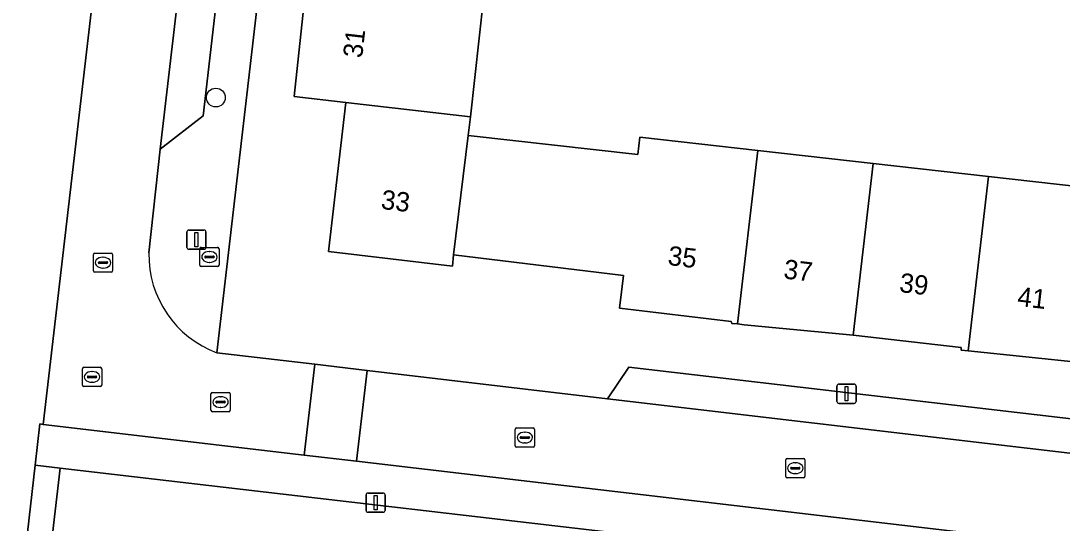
# Model space of a CAD drawing. Extents: x 161241 to 161758, y 384138 to 384885.
# Drawn here: x 161339.7 to 161393.7, y 384501.4 to 384527.4 of the extents above; entities that cross this region are included whole.
import ezdxf

# ---------------------------------------------------------------- set-up
doc = ezdxf.new("R2010")
doc.units = 0
for name, color, linetype in [('IMGEO_Boom', 7, 'Continuous'), ('IMGEO_Brandkraan', 7, 'Continuous'), ('IMGEO_Erf', 7, 'Continuous'), ('IMGEO_Kolk', 7, 'Continuous'), ('IMGEO_Lichtmast', 7, 'Continuous'), ('IMGEO_Pand', 7, 'Continuous'), ('IMGEO_Pand_nummerreeks', 7, 'Continuous'), ('IMGEO_Parkeervlak_open', 7, 'Continuous'), ('IMGEO_Rijbaan_lokaal_open', 7, 'Continuous'), ('IMGEO_Rioolput', 7, 'Continuous'), ('IMGEO_Voetpad_open', 7, 'Continuous')]:
    doc.layers.add(name, color=color, linetype=linetype)

msp = doc.modelspace()

# ---------------------------------------------------------------- linework, layer by layer
at = {"layer": 'IMGEO_Boom'}
msp.add_circle((161349.789, 384523.448), 0.489, dxfattribs=at)
at = {"layer": 'IMGEO_Brandkraan'}
for p, q in [((161348.955, 384514.751), (161348.955, 384515.603)), ((161349.03, 384515.677), (161349.882, 384515.677)), ((161349.443, 384515.457), (161349.468, 384515.457)), ((161349.956, 384515.603), (161349.956, 384514.751)), ((161349.214, 384515.171), (161349.214, 384515.183)), ((161349.652, 384515.134), (161349.254, 384515.134)), ((161349.257, 384515.22), (161349.655, 384515.22)), ((161349.466, 384514.897), (161349.441, 384514.897)), ((161349.698, 384515.183), (161349.698, 384515.171)), ((161349.882, 384514.677), (161349.03, 384514.677))]:
    msp.add_line(p, q, dxfattribs=at)
for points in [[(161348.955, 384514.751), (161348.955, 384515.603)], [(161349.03, 384515.677), (161349.882, 384515.677)], [(161349.956, 384515.603), (161349.956, 384514.751)], [(161349.882, 384514.677), (161349.03, 384514.677)]]:
    msp.add_lwpolyline(points, dxfattribs=at)
for centre, radius, start, end in [((161349.032, 384515.601), 0.0765, 91.552, 178.448), ((161349.032, 384515.601), 0.0765, 91.552, 178.448), ((161349.88, 384515.601), 0.0765, 1.552, 88.448), ((161349.88, 384515.601), 0.0765, 1.552, 88.448), ((161349.254, 384515.18), 0.0403, 85.8775, 175.7526), ((161349.251, 384515.17), 0.0366, 178.938, 274.7102), ((161349.655, 384515.177), 0.043, 264.8664, 352.4533), ((161349.659, 384515.182), 0.0386, 1.7309, 96.639), ((161349.032, 384514.753), 0.0765, 181.552, 268.448), ((161349.032, 384514.753), 0.0765, 181.552, 268.448), ((161349.88, 384514.753), 0.0765, 271.552, 358.448), ((161349.88, 384514.753), 0.0765, 271.552, 358.448)]:
    msp.add_arc(centre, radius, start, end, dxfattribs=at)
for centre, major_axis, ratio, start_param, end_param in [((161349.442, 384515.177), (-0.387, 0.002), 0.722429, 4.712389, 7.853982), ((161349.467, 384515.177), (-0.39, 0.002), 0.717154, 1.570796, 4.712389)]:
    msp.add_ellipse(centre, major_axis=major_axis, ratio=ratio, start_param=start_param, end_param=end_param, dxfattribs=at)
at = {"layer": 'IMGEO_Erf'}
for points in [[(161332.131, 384432.245), (161332.897, 384438.907), (161336.632, 384471.394), (161336.946, 384474.139), (161340.403, 384504.377), (161340.647, 384506.515), (161340.82, 384506.489), (161349.943, 384584.816), (161350.191, 384586.943), (161382.92, 384583.217)], [(161353.642, 384542.948), (161349.844, 384510.209), (161354.929, 384509.609), (161357.65, 384509.288), (161370.122, 384507.816), (161371.245, 384509.461), (161423.885, 384503.32), (161424.463, 384501.437), (161427.862, 384501.04), (161430.603, 384500.72), (161436.769, 384500)], [(161363.697, 384528.581), (161363.009, 384522.448), (161362.9, 384521.481), (161371.708, 384520.492), (161371.808, 384521.386), (161377.931, 384520.699), (161383.926, 384520.026), (161389.92, 384519.353), (161395.914, 384518.68), (161401.908, 384518.007), (161407.903, 384517.334), (161413.897, 384516.661), (161419.892, 384515.989), (161426.097, 384515.292), (161425.996, 384514.397), (161434.78, 384513.411), (161434.849, 384514.022), (161435.538, 384520.166), (161436.213, 384526.177), (161436.887, 384532.189)], [(161394.858, 384509.685), (161388.859, 384510.31), (161388.492, 384510.348), (161388.492, 384510.475), (161382.88, 384511.115), (161377.225, 384511.664), (161376.875, 384511.701), (161376.584, 384511.732), (161376.552, 384511.837), (161370.746, 384512.522), (161370.953, 384514.221), (161362.13, 384515.29), (161362.078, 384514.704), (161355.646, 384515.453), (161356.534, 384523.195), (161353.849, 384523.505), (161354.513, 384529.66)], [(161377.935, 384500), (161341.704, 384504.225), (161338.179, 384473.999)]]:
    msp.add_lwpolyline(points, dxfattribs=at)
at = {"layer": 'IMGEO_Kolk'}
for p, q in [((161343.502, 384515.382), (161344.354, 384515.382)), ((161343.427, 384514.456), (161343.427, 384515.308)), ((161343.686, 384514.876), (161343.686, 384514.888)), ((161344.124, 384514.839), (161343.726, 384514.839)), ((161343.729, 384514.925), (161344.127, 384514.925)), ((161343.915, 384515.162), (161343.94, 384515.162)), ((161344.17, 384514.888), (161344.17, 384514.876)), ((161344.428, 384515.308), (161344.428, 384514.456)), ((161344.354, 384514.382), (161343.502, 384514.382)), ((161343.938, 384514.602), (161343.913, 384514.602)), ((161349.535, 384507.22), (161349.535, 384508.072)), ((161349.61, 384508.146), (161350.462, 384508.146)), ((161350.023, 384507.926), (161350.048, 384507.926)), ((161350.536, 384508.072), (161350.536, 384507.22)), ((161349.794, 384507.64), (161349.794, 384507.652)), ((161350.232, 384507.603), (161349.834, 384507.603)), ((161349.837, 384507.689), (161350.235, 384507.689)), ((161350.046, 384507.366), (161350.021, 384507.366)), ((161350.278, 384507.652), (161350.278, 384507.64)), ((161350.462, 384507.146), (161349.61, 384507.146)), ((161365.337, 384505.38), (161365.337, 384506.232)), ((161365.412, 384506.306), (161366.264, 384506.306)), ((161366.338, 384506.232), (161366.338, 384505.38)), ((161365.596, 384505.8), (161365.596, 384505.812)), ((161366.034, 384505.763), (161365.636, 384505.763)), ((161365.639, 384505.849), (161366.037, 384505.849)), ((161365.825, 384506.086), (161365.85, 384506.086)), ((161366.08, 384505.812), (161366.08, 384505.8)), ((161366.264, 384505.306), (161365.412, 384505.306)), ((161365.848, 384505.526), (161365.823, 384505.526)), ((161379.383, 384503.792), (161379.383, 384504.644)), ((161379.458, 384504.718), (161380.31, 384504.718)), ((161380.384, 384504.644), (161380.384, 384503.792)), ((161379.642, 384504.212), (161379.642, 384504.224)), ((161380.08, 384504.175), (161379.682, 384504.175)), ((161379.685, 384504.261), (161380.083, 384504.261)), ((161379.871, 384504.498), (161379.896, 384504.498)), ((161380.126, 384504.224), (161380.126, 384504.212)), ((161380.31, 384503.718), (161379.458, 384503.718)), ((161379.894, 384503.938), (161379.869, 384503.938))]:
    msp.add_line(p, q, dxfattribs=at)
for points in [[(161343.502, 384515.382), (161344.354, 384515.382)], [(161343.427, 384514.456), (161343.427, 384515.308)], [(161344.428, 384515.308), (161344.428, 384514.456)], [(161344.354, 384514.382), (161343.502, 384514.382)], [(161349.535, 384507.22), (161349.535, 384508.072)], [(161349.61, 384508.146), (161350.462, 384508.146)], [(161350.536, 384508.072), (161350.536, 384507.22)], [(161350.462, 384507.146), (161349.61, 384507.146)], [(161365.337, 384505.38), (161365.337, 384506.232)], [(161365.412, 384506.306), (161366.264, 384506.306)], [(161366.338, 384506.232), (161366.338, 384505.38)], [(161366.264, 384505.306), (161365.412, 384505.306)], [(161379.383, 384503.792), (161379.383, 384504.644)], [(161379.458, 384504.718), (161380.31, 384504.718)], [(161380.384, 384504.644), (161380.384, 384503.792)], [(161380.31, 384503.718), (161379.458, 384503.718)]]:
    msp.add_lwpolyline(points, dxfattribs=at)
for centre, radius, start, end in [((161343.504, 384515.306), 0.0765, 91.552, 178.448), ((161343.504, 384515.306), 0.0765, 91.552, 178.448), ((161344.352, 384515.306), 0.0765, 1.552, 88.448), ((161344.352, 384515.306), 0.0765, 1.552, 88.448), ((161343.726, 384514.885), 0.0403, 85.8775, 175.7526), ((161343.723, 384514.875), 0.0366, 178.938, 274.7102), ((161344.127, 384514.882), 0.043, 264.8664, 352.4533), ((161344.131, 384514.887), 0.0386, 1.7309, 96.639), ((161343.504, 384514.458), 0.0765, 181.552, 268.448), ((161343.504, 384514.458), 0.0765, 181.552, 268.448), ((161344.352, 384514.458), 0.0765, 271.552, 358.448), ((161344.352, 384514.458), 0.0765, 271.552, 358.448), ((161349.612, 384508.07), 0.0765, 91.552, 178.448), ((161349.612, 384508.07), 0.0765, 91.552, 178.448), ((161350.46, 384508.07), 0.0765, 1.552, 88.448), ((161350.46, 384508.07), 0.0765, 1.552, 88.448), ((161349.834, 384507.649), 0.0403, 85.8775, 175.7526), ((161349.831, 384507.639), 0.0366, 178.938, 274.7102), ((161350.235, 384507.646), 0.043, 264.8664, 352.4533), ((161350.239, 384507.651), 0.0386, 1.7309, 96.639), ((161349.612, 384507.222), 0.0765, 181.552, 268.448), ((161349.612, 384507.222), 0.0765, 181.552, 268.448), ((161350.46, 384507.222), 0.0765, 271.552, 358.448), ((161350.46, 384507.222), 0.0765, 271.552, 358.448), ((161365.414, 384506.23), 0.0765, 91.552, 178.448), ((161365.414, 384506.23), 0.0765, 91.552, 178.448), ((161366.262, 384506.23), 0.0765, 1.552, 88.448), ((161366.262, 384506.23), 0.0765, 1.552, 88.448), ((161365.636, 384505.809), 0.0403, 85.8775, 175.7526), ((161365.633, 384505.799), 0.0366, 178.938, 274.7102), ((161366.037, 384505.806), 0.043, 264.8664, 352.4533), ((161366.041, 384505.811), 0.0386, 1.7309, 96.639), ((161365.414, 384505.382), 0.0765, 181.552, 268.448), ((161365.414, 384505.382), 0.0765, 181.552, 268.448), ((161366.262, 384505.382), 0.0765, 271.552, 358.448), ((161366.262, 384505.382), 0.0765, 271.552, 358.448), ((161379.46, 384504.642), 0.0765, 91.552, 178.448), ((161379.46, 384504.642), 0.0765, 91.552, 178.448), ((161380.308, 384504.642), 0.0765, 1.552, 88.448), ((161380.308, 384504.642), 0.0765, 1.552, 88.448), ((161379.682, 384504.221), 0.0403, 85.8775, 175.7526), ((161379.679, 384504.211), 0.0366, 178.938, 274.7102), ((161380.083, 384504.218), 0.043, 264.8664, 352.4533), ((161380.087, 384504.223), 0.0386, 1.7309, 96.639), ((161379.46, 384503.794), 0.0765, 181.552, 268.448), ((161379.46, 384503.794), 0.0765, 181.552, 268.448), ((161380.308, 384503.794), 0.0765, 271.552, 358.448), ((161380.308, 384503.794), 0.0765, 271.552, 358.448)]:
    msp.add_arc(centre, radius, start, end, dxfattribs=at)
for centre, major_axis, ratio, start_param, end_param in [((161343.914, 384514.882), (-0.387, 0.002), 0.722429, 4.712389, 7.853982), ((161343.939, 384514.882), (-0.39, 0.002), 0.717154, 1.570796, 4.712389), ((161350.022, 384507.646), (-0.387, 0.002), 0.722429, 4.712389, 7.853982), ((161350.047, 384507.646), (-0.39, 0.002), 0.717154, 1.570796, 4.712389), ((161365.824, 384505.806), (-0.387, 0.002), 0.722429, 4.712389, 7.853982), ((161365.849, 384505.806), (-0.39, 0.002), 0.717154, 1.570796, 4.712389), ((161379.87, 384504.218), (-0.387, 0.002), 0.722429, 4.712389, 7.853982), ((161379.895, 384504.218), (-0.39, 0.002), 0.717154, 1.570796, 4.712389)]:
    msp.add_ellipse(centre, major_axis=major_axis, ratio=ratio, start_param=start_param, end_param=end_param, dxfattribs=at)
at = {"layer": 'IMGEO_Lichtmast'}
for p, q in [((161348.283, 384515.674), (161348.283, 384516.474)), ((161348.283, 384516.474), (161348.283, 384515.674)), ((161348.383, 384516.574), (161349.173, 384516.574)), ((161349.173, 384516.574), (161348.383, 384516.574)), ((161349.273, 384516.474), (161349.273, 384515.674)), ((161349.273, 384515.674), (161349.273, 384516.474)), ((161349.173, 384515.574), (161348.383, 384515.574)), ((161348.383, 384515.574), (161349.173, 384515.574)), ((161382.048, 384507.68), (161382.048, 384508.48)), ((161382.048, 384508.48), (161382.048, 384507.68)), ((161382.148, 384508.58), (161382.938, 384508.58)), ((161382.938, 384508.58), (161382.148, 384508.58)), ((161383.038, 384508.48), (161383.038, 384507.68)), ((161383.038, 384507.68), (161383.038, 384508.48)), ((161382.938, 384507.58), (161382.148, 384507.58)), ((161382.148, 384507.58), (161382.938, 384507.58)), ((161357.689, 384502.927), (161358.479, 384502.927)), ((161358.479, 384502.927), (161357.689, 384502.927)), ((161357.589, 384502.027), (161357.589, 384502.827)), ((161357.589, 384502.827), (161357.589, 384502.027)), ((161358.579, 384502.827), (161358.579, 384502.027)), ((161358.579, 384502.027), (161358.579, 384502.827)), ((161358.479, 384501.927), (161357.689, 384501.927)), ((161357.689, 384501.927), (161358.479, 384501.927))]:
    msp.add_line(p, q, dxfattribs=at)
for points in [[(161348.703, 384516.449), (161348.853, 384516.449), (161348.853, 384515.699), (161348.703, 384515.699), (161348.703, 384516.449)], [(161382.468, 384508.455), (161382.618, 384508.455), (161382.618, 384507.705), (161382.468, 384507.705), (161382.468, 384508.455)], [(161358.009, 384502.802), (161358.159, 384502.802), (161358.159, 384502.052), (161358.009, 384502.052), (161358.009, 384502.802)]]:
    msp.add_lwpolyline(points, dxfattribs=at)
for centre, start, end in [((161348.383, 384516.474), 90, 180), ((161348.383, 384516.474), 90, 180), ((161349.173, 384516.474), 0, 90), ((161349.173, 384516.474), 360, 90), ((161348.383, 384515.674), 180, 270), ((161348.383, 384515.674), 180, 270), ((161349.173, 384515.674), 270, 0), ((161349.173, 384515.674), 270, 0), ((161382.148, 384508.48), 90, 180), ((161382.148, 384508.48), 90, 180), ((161382.938, 384508.48), 0, 90), ((161382.938, 384508.48), 360, 90), ((161382.148, 384507.68), 180, 270), ((161382.148, 384507.68), 180, 270), ((161382.938, 384507.68), 270, 0), ((161382.938, 384507.68), 270, 0), ((161357.689, 384502.827), 90, 180), ((161357.689, 384502.827), 90, 180), ((161358.479, 384502.827), 0, 90), ((161358.479, 384502.827), 360, 90), ((161357.689, 384502.027), 180, 270), ((161357.689, 384502.027), 180, 270), ((161358.479, 384502.027), 270, 0), ((161358.479, 384502.027), 270, 0)]:
    msp.add_arc(centre, 0.1, start, end, dxfattribs=at)
at = {"layer": 'IMGEO_Pand'}
for points in [[(161354.513, 384529.66), (161353.849, 384523.505), (161356.534, 384523.195), (161363.009, 384522.448), (161363.697, 384528.581)], [(161362.9, 384521.481), (161363.009, 384522.448), (161356.534, 384523.195), (161355.646, 384515.453), (161362.078, 384514.704), (161362.13, 384515.29)], [(161377.931, 384520.699), (161371.808, 384521.386), (161371.708, 384520.492), (161362.9, 384521.481), (161362.13, 384515.29), (161370.953, 384514.221), (161370.746, 384512.522), (161376.552, 384511.837), (161376.584, 384511.732), (161376.875, 384511.701)], [(161376.875, 384511.701), (161377.225, 384511.664), (161382.88, 384511.115), (161383.926, 384520.026), (161377.931, 384520.699)], [(161389.92, 384519.353), (161383.926, 384520.026), (161382.88, 384511.115), (161388.492, 384510.475), (161388.492, 384510.348), (161388.859, 384510.31)], [(161388.859, 384510.31), (161394.858, 384509.685), (161395.914, 384518.68), (161389.92, 384519.353)]]:
    msp.add_lwpolyline(points, close=True, dxfattribs=at)
at = {"layer": 'IMGEO_Parkeervlak_open'}
for points in [[(161346.902, 384520.776), (161349.128, 384522.508), (161351.24, 384540.794), (161349.456, 384542.683)], [(161370.122, 384507.816), (161424.463, 384501.437), (161423.885, 384503.32), (161371.245, 384509.461)]]:
    msp.add_lwpolyline(points, close=True, dxfattribs=at)
at = {"layer": 'IMGEO_Rijbaan_lokaal_open'}
for points in [[(161382.841, 384581.101), (161349.943, 384584.816), (161340.82, 384506.489), (161354.376, 384504.9), (161354.929, 384509.609), (161349.844, 384510.209)], [(161346.307, 384515.385), (161346.902, 384520.776), (161349.456, 384542.683), (161350.099, 384548.19), (161352.715, 384570.865), (161353.233, 384575.354)]]:
    msp.add_lwpolyline(points, dxfattribs=at)
for points in [[(161357.65, 384509.288), (161354.929, 384509.609), (161354.376, 384504.9), (161357.097, 384504.581)], [(161357.65, 384509.288), (161357.097, 384504.581), (161396.178, 384500), (161427.321, 384496.383), (161427.741, 384500), (161427.862, 384501.04), (161424.463, 384501.437), (161370.122, 384507.816)]]:
    msp.add_lwpolyline(points, close=True, dxfattribs=at)
msp.add_arc((161351.73, 384515.294), 5.423, 179.0396, 249.6536, dxfattribs=at)
at = {"layer": 'IMGEO_Rioolput'}
for p, q in [((161342.933, 384509.455), (161343.785, 384509.455)), ((161342.858, 384508.529), (161342.858, 384509.381)), ((161343.117, 384508.949), (161343.117, 384508.961)), ((161343.555, 384508.912), (161343.157, 384508.912)), ((161343.16, 384508.998), (161343.558, 384508.998)), ((161343.346, 384509.235), (161343.371, 384509.235)), ((161343.601, 384508.961), (161343.601, 384508.949)), ((161343.859, 384509.381), (161343.859, 384508.529)), ((161343.785, 384508.455), (161342.933, 384508.455)), ((161343.369, 384508.675), (161343.344, 384508.675))]:
    msp.add_line(p, q, dxfattribs=at)
for points in [[(161342.933, 384509.455), (161343.785, 384509.455)], [(161342.858, 384508.529), (161342.858, 384509.381)], [(161343.859, 384509.381), (161343.859, 384508.529)], [(161343.785, 384508.455), (161342.933, 384508.455)]]:
    msp.add_lwpolyline(points, dxfattribs=at)
for centre, radius, start, end in [((161342.935, 384509.379), 0.0765, 91.552, 178.448), ((161342.935, 384509.379), 0.0765, 91.552, 178.448), ((161343.783, 384509.379), 0.0765, 1.552, 88.448), ((161343.783, 384509.379), 0.0765, 1.552, 88.448), ((161343.157, 384508.958), 0.0403, 85.8775, 175.7526), ((161343.154, 384508.948), 0.0366, 178.938, 274.7102), ((161343.558, 384508.955), 0.043, 264.8664, 352.4533), ((161343.562, 384508.96), 0.0386, 1.7309, 96.639), ((161342.935, 384508.531), 0.0765, 181.552, 268.448), ((161342.935, 384508.531), 0.0765, 181.552, 268.448), ((161343.783, 384508.531), 0.0765, 271.552, 358.448), ((161343.783, 384508.531), 0.0765, 271.552, 358.448)]:
    msp.add_arc(centre, radius, start, end, dxfattribs=at)
for centre, major_axis, ratio, start_param, end_param in [((161343.345, 384508.955), (-0.387, 0.002), 0.722429, 4.712389, 7.853982), ((161343.37, 384508.955), (-0.39, 0.002), 0.717154, 1.570796, 4.712389)]:
    msp.add_ellipse(centre, major_axis=major_axis, ratio=ratio, start_param=start_param, end_param=end_param, dxfattribs=at)
at = {"layer": 'IMGEO_Voetpad_open'}
for points in [[(161353.233, 384575.354), (161352.715, 384570.865), (161352.928, 384570.84), (161354.523, 384569.051), (161352.281, 384549.796), (161350.099, 384548.19), (161349.456, 384542.683), (161351.24, 384540.794), (161349.128, 384522.508), (161346.902, 384520.776), (161346.307, 384515.385)], [(161349.844, 384510.209), (161353.642, 384542.948), (161354.08, 384546.72)]]:
    msp.add_lwpolyline(points, dxfattribs=at)
for points in [[(161430.062, 384496.065), (161427.321, 384496.383), (161396.178, 384500), (161357.097, 384504.581), (161354.376, 384504.9), (161340.82, 384506.489), (161340.647, 384506.515), (161340.403, 384504.377), (161341.704, 384504.225), (161377.935, 384500), (161395.453, 384497.957), (161401.111, 384497.3), (161421.466, 384494.929), (161433, 384493.585), (161437.975, 384493.006), (161442.515, 384492.47), (161448.511, 384491.779), (161454.323, 384491.094), (161500, 384485.79), (161510.344, 384484.589), (161510.654, 384486.641), (161500, 384487.889), (161448.776, 384493.891)], [(161341.704, 384504.225), (161340.403, 384504.377), (161336.946, 384474.139), (161338.179, 384473.999)]]:
    msp.add_lwpolyline(points, close=True, dxfattribs=at)
msp.add_arc((161351.73, 384515.294), 5.423, 179.0396, 249.6536, dxfattribs=at)

# ---------------------------------------------------------------- texts
at = {"layer": 'IMGEO_Pand_nummerreeks'}
for s, rotation, p in [('31', 83.3384, (161357.381, 384525.469)), ('33', 353.3579, (161358.332, 384517.677)), ('35', 353.3314, (161373.225, 384514.769)), ('37', 353.3314, (161379.24, 384514.066)), ('39', 353.3314, (161385.254, 384513.362)), ('41', 353.3314, (161391.381, 384512.646))]:
    msp.add_text(s, height=1, rotation=rotation, dxfattribs=at).set_placement(p)

doc.saveas('drawing.dxf')
